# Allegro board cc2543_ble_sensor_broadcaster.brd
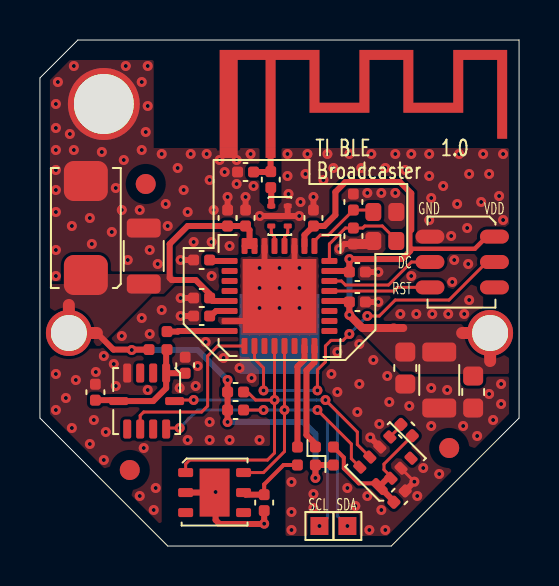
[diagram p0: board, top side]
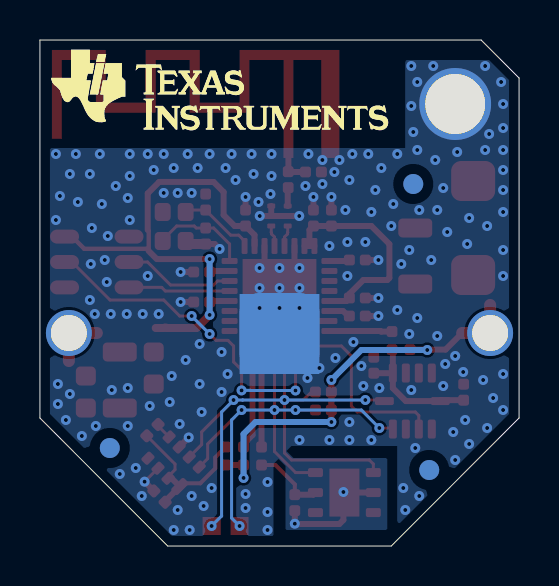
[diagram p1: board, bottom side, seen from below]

Outline 24 x 25.3 mm; copper layers: TOP, BOTTOM. Coordinates in mm from the lower left corner of the outline.
Outline path: 0,23.4 0,6.4 6.4,0 17.6,0 24,6.4 24,25.3 1.9,25.3 0,23.4

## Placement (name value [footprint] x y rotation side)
A1  2.4GHz  [ANTENNA_AN043CN]  11.55 19.65 0 top
BT1  3003  [BAT_3003C]  22.55 10.65 180 bottom
C2  22uF  [CAPC1608X90N]  18.3 9.7 270 top
C3  22uF  [CAPC1608X90N]  21.7 8.5 270 top
C4  100uF  [CAPC3216X180L]  5.2 13.1 90 top
C5  100uF  [CAPC3216X180L]  20 9.7 270 top
C6  470uF  [CAPMP6032X280L]  2.3 13.55 90 top
C21  100nF  [CAPC1005X60L]  11.23 2.57 270 top
C23  100nF  [CAPC1005X60L]  7.28 8.64 90 top
C24  1uF  [CAPC1005X60L]  2.78 7.29 90 top
C31  100nF  [CAPC1005X60L]  17.73 2.19 45 top
C41  DNM  [CAPC1005X60L]  10.7 18.7 180 top
C121  100nF  [CAPC1005X60L]  15.5 12.2 0 top
C151  100nF  [CAPC1005X60L]  15.5 13.7 0 top
C161  12pF  [CAPC1005X60L]  15.7 16.8 90 top
C171  12pF  [CAPC1005X60L]  15.7 15.9 270 top
C181  100nF  [CAPC1005X60L]  13.7 16 90 top
C231  220pF  [CAPC1005X60L]  9.4 16 90 top
C232  100nF  [CAPC1005X60L]  10.3 16 90 top
C291  100nF  [CAPC1005X60L]  8.5 12.4 180 top
C301  1uF  [CAPC1005X60L]  8.5 11.5 180 top
FIDU1  FIDU_1MM  [FID100X115]  5.3 18.1 0 top
FIDU2  FIDU_1MM  [FID100X115]  20.5 4.9 0 top
FIDU3  FIDU_1MM  [FID100X115]  4.5 3.8 0 top
FIDU4  FIDU_1MM  [FID100X115]  5.3 18.1 180 bottom
FIDU5  FIDU_1MM  [FID100X115]  20.5 4.9 180 bottom
FIDU6  FIDU_1MM  [FID100X115]  4.5 3.8 180 bottom
FL1  LFB182G45BG2D280  [FIL_LFB182G45BG2D280L]  11.59 17 270 top
J1  CLP-103-02-L-D  [SAMTEC_CLP10302LD-6L]  22.77 15.47 180 top
MH1  HOLE_3.0mm_PTH  [MTG300_360]  3.2 22.1 0 top
NOREF  -  []  0 17.03 0 top
NOREF#2  -  []  13.68 0 90 top
R1  4.7k  [RESC1005X40L]  10.2 7.7 180 top
R2  4.7k  [RESC1005X40L]  10.2 6.8 180 top
R11  0  [RESC1005X40BL]  6.36 9.82 180 top
R21  0  [RESC1005X40AL]  12.9 4.05 90 top
R31  0  [RESC1005X40BL]  14.7 4.95 270 top
R32  10k  [RESC1005X40L]  18.08 6.08 315 top
R41  0  [RESC1005X40L]  11.56 18.72 270 top
R251  56k  [RESC1005X40L]  7.7 14.3 0 top
TP1  TP_35SQU_SMD  [TP90SQWOPM_V2]  15.4 1 0 top
TP2  TP_35SQU_SMD  [TP90SQWOPM_V2]  14 1 0 top
U1  CC2543RHM  [QFNWB50P500X500X100-33CN]  10.25 10 0 top
U2  SHT21  [SON100P300X300X110-7L]  7.3 3.67 270 top
U3  T5400  [PSON71P223X278X75-8L]  16.99 2.97 45 top
U4  KXTF9  [QFNFC65P300X300X100-10N]  6.32 8.65 180 top
UNK#REFDES  -  []  22.44 24.82 180 bottom
X1  32MHz  [XTAL_FA128L]  16.7 16.7 270 top

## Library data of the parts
A1 = ANTENNA_AN043
BT1 = BATT_RETAINER: alternate symbols: (BAT_3003C,BAT_3003A)
C2 C3 = CAPACITOR: alternate symbols: (CAPC1608X90L,CAPC1608X90M)
C4 C5 = CAPACITOR: alternate symbols: (CAPC3216X180L,CAPC3216X180M)
C6 = CAPACITOR_POL: alternate symbols: (CAPMP6032X280L,CAPMP6032X280M)
C21 C23 C24 C31 C41 C121 C151 C161 C171 C181 C231 C232 C291 C301 = CAPACITOR: alternate symbols: (CAPC1005X60L,CAPC1005X60M)
FIDU1-FIDU6 = FIDMARK
FL1 = FILTER_LFB_6PIN: alternate symbols: (FIL_LFB182G45BG2D280L,FIL_LFB182G45BG2D280M)
J1 = CONN_HEADER_2X3: alternate symbols: (SAMTEC_CLP10302LD-6L,SAMTEC_CLP10302LD-6M)
MH1 = HOLE_PTH
R1 R2 R32 R41 R251 = RESISTOR: alternate symbols: (RESC1005X40L,RESC1005X40M)
R11 R21 R31 = RESISTOR_3PORTS: alternate symbols: (RESC1005X40AL,RESC1005X40AM,RESC1005X40BL,RESC1005X40BM)
TP1 TP2 = TEST_POINT
U1 = IC_RF_CC2543_QFN32_0: alternate symbols: (QFNWB50P500X500X100-33CL,QFNWB50P500X500X100-33CM)
U2 = IC_SENSOR_SHT21: alternate symbols: (SON100P300X300X110-7L,SON100P300X300X110-7M)
U3 = IC_PERIPH_T5400_PSON8: alternate symbols: (PSON71P223X278X75-8L,PSON71P223X278X75-8M)
U4 = IC_ACC_KXTF9_LGA10: alternate symbols: (QFNFC65P300X300X100-10,QFNFC65P300X300X100-10M)
X1 = XTAL_4: alternate symbols: (XTAL_FA128L,XTAL_FA128M)

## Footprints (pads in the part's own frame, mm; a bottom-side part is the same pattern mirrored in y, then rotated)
ANTENNA_AN043CN
  rect 0.5x0.5 smd: 1(0,0)
  rect 0.9x0.5 smd: 2(-2.1,0)
BAT_3003C
  round 2.3 hole 1.8: 1(0,0) 3(21.1,0)
  custom 1x1 smd: 2(10.55,0)
CAPC1005X60L
  custom 0.135x0.135 smd: 1(0,0) 2(0.8,0)
CAPC1608X90N
  custom 0.237x0.237 smd: 1(0,0) 2(1.6,0)
CAPC3216X180L
  custom 0.237x0.237 smd: 1(0,0) 2(2.8,0)
CAPMP6032X280L
  custom 0.5x0.5 smd: 1(0,0) 2(4.7,0)
FID100X115
  oval 1x1 smd: 1(0,0)
FIL_LFB182G45BG2D280L
  custom 0.062x0.062 smd: 1(0,0) 2(0.5,0) 3(1,0) 4(1,0.825) 5(0.5,0.825) 6(0,0.825)
MTG300_360
  round 3.6 hole 3: 1(0,0)
PSON71P223X278X75-8L
  custom 0.113x0.113 smd: 1(0,0) 2(0.71,-0.125) 3(1.42,-0.125) 4(2.13,-0.125) 5(2.13,1.375) 6(1.42,1.375) 7(0.71,1.375) 8(0,1.375)
QFNFC65P300X300X100-10N
  custom 0.1x0.1 smd: 1(0,0) 2(0.65,0) 3(1.3,0) 4(1.95,0) 5(2.375,1.4) 6(1.95,2.8) 7(1.3,2.8) 8(0.65,2.8) 9(0,2.8) 10(-0.425,1.4)
QFNWB50P500X500X100-33CN
  custom 0.075x0.075 smd: 1(0,0) 2(0.5,0) 3(1,0) 4(1.5,0) 5(2,0) 6(2.5,0) 7(3,0) 8(3.5,0) 9(4.25,0.75) 10(4.25,1.25) 11(4.25,1.75) 12(4.25,2.25) 13(4.25,2.75) 14(4.25,3.25) 15(4.25,3.75) 16(4.25,4.25) 17(3.5,5) 18(3,5) 19(2.5,5) 20(2,5) 21(1.5,5) 22(1,5) 23(0.5,5) 24(0,5) 25(-0.75,4.25) 26(-0.75,3.75) 27(-0.75,3.25) 28(-0.75,2.75) 29(-0.75,2.25) 30(-0.75,1.75) 31(-0.75,1.25) 32(-0.75,0.75)
  rect 3.7x3.7 smd: 33(1.75,2.5)
RESC1005X40AL
  custom 0.135x0.135 smd: 1(0,-0.9) 2(0,0) 3(0.9,0)
RESC1005X40BL
  custom 0.135x0.135 smd: 1(0,-0.9) 2(0,0) 3(0.9,0)
RESC1005X40L
  custom 0.135x0.135 smd: 1(0,0) 2(0.8,0)
SAMTEC_CLP10302LD-6L
  oval 1.45x0.7 smd: 1(0,0) 2(3.23,0) 3(0,1.27) 4(3.23,1.27) 5(0,2.54) 6(3.23,2.54)
SON100P300X300X110-7L
  custom 0.113x0.113 smd: 1(0,0) 2(1,0) 3(2,0) 4(2,2.9) 5(1,2.9) 6(0,2.9)
  rect 2.4x1.5 smd: 7(1,1.45)
TP90SQWOPM_V2
  rect 0.9x0.9 smd: 1(0,0)
XTAL_FA128L
  custom 0.2x0.2 smd: 1(0,0) 2(1.45,0) 3(1.45,1.15) 4(0,1.15)

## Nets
GND: A1.2(FEED) BT1.2(-) C2.2 C3.2 C4.2 C5.2 C6.2 C21.2 C23.2 C24.2 C31.2 C41.2 C121.2 C151.2 C161.2 C171.2 C181.2 C231.2 C232.2 C291.2 C301.2 FL1.2(GND#2) FL1.5(GND#5) FL1.6(GND#6) J1.2 MH1.1 R251.1 U1.19(VSS#19) U1.22(VSS#22) U1.31(VSS#31) U1.33(VSS/EGP) U2.2(VSS) U2.7(EGP) U3.3(GND) U3.6(MISO) U4.4(GND) X1.2 X1.4
VDD: BT1.1(+#1) BT1.3(+#3) C2.1 C3.1 C4.1 C5.1 C6.1 C121.1 C151.1 C181.1 C231.1 C232.1 C291.1 J1.1 R1.2 R2.2 R11.3 R21.1 R31.3 U1.12(VDD#12) U1.15(VDD#15) U1.18(VDD#18) U1.23(VDD#23) U1.24(VDD#24) U1.29(VDD#29)
ACC_INT: U1.1(P1_3) U4.7(INT)
ACC_POWER: R11.1 U1.32(P1_4)
DC: J1.4 U1.14(P2_2/DC)
DD: J1.3 U1.2(P2_1/DD)
HUM_POWER: R21.3 U1.7(P0_4)
PRS_POWER: R31.1 U1.8(P0_3)
RESET_N: J1.6 U1.13(NRESET)
SCL: R2.1 TP2.1 U1.5(P0_6) U2.6(SCL) U3.8(SCL/SCLK) U4.9(SCL)
SDA: R1.1 TP1.1 U1.4(P0_7) U2.1(SDA) U3.7(SDA/MOSI) U4.10(SDA)
N174685: FL1.4(BP2) U1.20(RF_P)
N174700: FL1.3(BP1) U1.21(RF_N)
N176560: R251.2 U1.25(RBIAS)
N176676: C301.1 U1.30(DCPL1)
N177477: C161.1 U1.17(XOSC_Q2) X1.1
N177564: C171.1 U1.16(XOSC_Q1) X1.3
N205771: C21.1 R21.2 U2.5(VDD)
N205894: C31.1 R31.2 R32.2 U3.1(VDD) U3.2(SEL)
N306707: FL1.1(UBP) R41.2
N306709: A1.1(GND) C41.1 R41.1
N309917: C23.1 C24.1 R11.2 U4.1(IOVDD) U4.5(VDD)
N318900: R32.1 U3.5(RST/SS)

Pads without a net: FIDU1 1; FIDU2 1; FIDU3 1; FIDU4 1; FIDU5 1; FIDU6 1; J1 5; U1 3 6 9 10 11 26 27 28; U2 3 4; U3 4; U4 2 3 6 8

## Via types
v1: diameter 0.5, hole 0.2, TOP to BOTTOM, 206 vias

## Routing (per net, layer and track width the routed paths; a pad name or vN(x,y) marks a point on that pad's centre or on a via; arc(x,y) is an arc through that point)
GND: length 26.5
  TOP w0.15: 18.09,3.88 v1(18.76,3.21)
  TOP w0.3: C291.2 v1(7.05,12.4) ; 18.29,2.75 v1(18.76,3.21) ; R251.1 v1(7.05,14.3) ; U1.19 12.75,13.25 U1.33 ; 11.23,1.77 v1(11.23,1.12) 11.22,1.1 9,1.1 8.8,1.3 8.8,2.62 U2.7 U2.2 ; C231.2 v1(9.4,17.45) ; FL1.5 FL1.6 ; FL1.5 FL1.2 v1(11.01,16.5) ; FL1.5 v1(12.99,16.5) ; U1.33 10.75,11.25 U1.31 ; U1.33 11.25,13.25 U1.22 ; U3.3 18.09,3.88 ; v1(15,14.85) 15.25,15.1 C171.2 ; C151.2 v1(16.95,13.7) ; C232.2 v1(10.3,17.45) ; C301.2 v1(7.05,11.5) ; 17.03,4.95 v1(16.55,5.43) ; C121.2 v1(16.95,12.2) ; C181.2 v1(13.7,17.45)
  TOP w0.5: C171.2 16.55,15.1 X1.2
  vias: v1(0.8,22.1) v1(0.8,20.9) v1(0.8,19.8) v1(0.8,18.8) v1(0.8,17.8) v1(0.8,16.7) v1(0.8,14.8) v1(0.8,13.5) v1(0.8,8.6) v1(0.8,6.8) v1(0.9,23.2) v1(1.3,7.4) v1(1.5,20.6) v1(1.6,16) v1(1.6,5.9) v1(1.7,24) v1(1.7,19.8) v1(1.8,8.3) v1(2.5,16.4) v1(2.5,5.1) v1(2.6,15.1) v1(2.7,6.3) v1(2.8,8.7) v1(3.1,19.7) v1(3.2,9.5) v1(3.2,4.3) v1(3.3,5.7) v1(3.6,15.7) v1(3.7,9.1) v1(3.8,17.9) v1(3.8,8) v1(4.1,16.8) v1(4.1,10.5) v1(4.2,19.3) v1(4.3,24) v1(4.4,14.3) v1(5,16.8) v1(5,2.5) v1(5.1,23.2) v1(5.1,19.8) v1(5.1,11.4) v1(5.2,4.9) v1(5.3,20.7) v1(5.4,24) v1(5.4,22) v1(5.4,7.8) v1(5.5,14.8) v1(5.5,10.6) v1(5.7,1.8) v1(5.8,2.9) v1(5.9,14.1) v1(6.1,19.6) v1(6.1,11.8) v1(6.3,17.1) v1(6.4,16) v1(6.9,18.9) v1(7,7.9) v1(7.2,17.8) v1(7.4,16.7) v1(7.4,5.3) v1(7.55,19.6) v1(7.7,15.2) v1(7.8,8) v1(7.9,9) v1(8.3,10.2) v1(8.35,19.6) v1(8.5,18.3) v1(8.5,6.2) v1(8.5,5.3) v1(8.6,15.2) v1(8.6,13.5) v1(8.7,16.8) v1(8.8,2.7) v1(9,19.3) v1(9.2,9.4) v1(9.25,18.7) v1(9.5,15) v1(9.5,5.3) v1(9.85,19.3) v1(9.85,18.1) v1(10,8.9) v1(10.55,19.6) v1(10.6,8.4) v1(10.7,18) v1(11,13.9) v1(11,12.9) v1(11,11.9) v1(11,5.3) v1(12,13.9) v1(12,12.9) v1(12,11.9) v1(12.4,19.6) v1(12.4,18.5) v1(12.45,17.6) v1(12.6,3.2) v1(12.6,1.7) v1(12.6,0.8) v1(13,13.9) v1(13,12.9) v1(13,11.9) v1(13.05,17.2) v1(13.3,18.6) v1(13.4,19.6) v1(13.7,2.6) v1(13.7,1.9) v1(14.2,18.3) v1(14.4,19.6) v1(14.6,8.6) v1(14.7,18.9) v1(14.9,9.7) v1(14.9,7.7) v1(15.4,2.9) v1(15.5,19.6) v1(15.8,2) v1(15.9,6.7) v1(16,10.1) v1(16,8.1) v1(16.1,18.9) v1(16.4,17.65) v1(16.4,2.5) v1(16.5,0.8) v1(16.6,19.6) v1(16.7,9.3) v1(17,6.1) v1(17.1,17.65) v1(17.1,1.8) v1(17.3,18.9) v1(17.3,0.8) v1(17.4,8.5) v1(17.5,7.2) v1(17.8,19.6) v1(17.8,17.65) v1(18.05,11.6) v1(18.3,18.8) v1(18.5,7) v1(18.6,19.6) v1(18.6,13.5) v1(18.85,11.6) v1(18.9,2.5) v1(19.2,3.9) v1(19.5,19.6) v1(19.5,18.5) v1(19.5,16.3) v1(19.6,17.4) v1(19.6,7.9) v1(19.6,6) v1(19.65,11.6) v1(20,3.6) v1(20.2,18) v1(20.4,7.8) v1(20.45,11.6) v1(20.6,15.5) v1(20.65,13.2) v1(20.75,14.3) v1(20.9,17.1) v1(21,19.6) v1(21.2,6) v1(21.25,11.6) v1(21.4,15.9) v1(21.5,18.6) v1(21.45,14.1) v1(21.5,12.3) v1(21.9,5.5) v1(22.1,17.2) v1(22.2,19.6) v1(22.5,18.6) v1(22.5,7.6) v1(22.7,6.3) v1(23,17.5) v1(23.1,8.1) v1(23.1,7.1) v1(23.2,19.6) v1(23.2,16.3)
VDD: length 64.4
  TOP w0.15: 3.68,9.82 3.7,9.8 v1(4.6,9.8) ; C3.1 21.7,8.7
  TOP w0.22: J1.1 22.39,15.47 21.78,14.86 18.66,14.86 18.55,14.75 18.55,15.75 18.6,15.8 ; 18.15,14.35 18.1,14.35
  TOP w0.3: 18.1,14.35 v1(15.5,14.35) C151.1 ; R11.3 3.68,9.82 2.85,10.65 ; 10.5,15 10.5,15.8 C232.1 C231.1 7.4,16 6.5,15.1 6.5,13.4 6.6,13.3 7.8,13.3 8.5,12.6 C291.1 8.65,12.25 U1.29 ; 10.5,15 U1.24 ; 10.5,15 U1.23 ; C151.1 15.45,13.65 ; C151.1 15.45,13.75 U1.15 ; U1.18 13.25,15.55 C181.1 14.25,16 14.8,16.55 14.8,17.7 15.3,18.2 16.17,18.2 16.17,18.2 18.03,18.2 18.6,17.63 18.6,15.8 ; U1.12 15.45,12.25 C121.1 ; v1(9.4,6.2) R2.2 R1.2 v1(9.4,8.3) ; C121.1 v1(15.5,11.55) ; C121.1 15.45,12.15 ; 18.55,14.75 18.15,14.35 ; R31.3 R21.1 v1(13.8,3.4)
  TOP w0.4: 18.2,10.9 17.83,10.9 17.76,10.91 17.67,10.91 17.61,10.9 17.6,10.9 16.2,10.9 ; 16.15,10.9 15.55,11.5 15.55,11.51 v1(15.5,11.55)
  TOP w0.6: 22.55,9.25 BT1.1 21.15,10.65 ; 2.85,10.65 BT1.3 1.45,12.05
  BOTTOM w0.3: v1(9.4,8.3) 7.9,9.8 v1(4.6,9.8) ; v1(9.4,6.2) 13.2,6.2 13.8,5.6 v1(13.8,3.4) ; v1(15.5,11.55) v1(15.5,14.35)
ACC_INT: length 8.8
  TOP w0.15: U1.1 8.9,10 8.4,9.5 8.4,7 8.1,6.7 5.2,6.7 5.02,6.52 U4.7
ACC_POWER: length 3.1
  TOP w0.3: U1.32 6.94,10.75 6.91,10.72 R11.1
DC: length 5.6
  TOP w0.15: U1.14 15.1,13.25 15.3,13.05 17.46,13.05 18.61,14.2 J1.4
DD: length 17.7
  TOP w0.15: v1(15.5,10.6) 15.18,10.28 14.58,10.28 14.3,10 14.3,9.2 13.9,8.8 v1(13.9,7.78) ; v1(11.2,7.77) 11.2,8.9 10.75,9.35 U1.2 ; v1(16.4,11.5) 17,11.5 17.8,12.3 20.49,12.3 22.39,14.2 J1.3
  BOTTOM w0.15: v1(15.5,10.6) v1(16.4,11.5) ; v1(11.2,7.77) 13.44,7.77 13.45,7.78 v1(13.9,7.78)
HUM_POWER: length 5.2
  TOP w0.3: U1.7 13.25,9.32 12.9,8.97 R21.3
PRS_POWER: length 5.4
  TOP w0.3: R31.1 13.8,5.1 13.35,5.55 13.35,8.79 13.75,9.18 U1.8
RESET_N: length 5.1
  TOP w0.15: U1.13 17.72,12.75 17.9,12.93 J1.6
SCL: length 26.6
  TOP w0.15: v1(11.2,6.8) R2.1 ; U4.9 6.38,5.9 v1(7,5.9) ; U2.6 11.2,3.67 12.25,4.73 v1(12.25,6.8) U1.5 ; 16.02,3.94 15.6,4.37 15.6,5.1 v1(13.9,6.8)
  BOTTOM w0.15: v1(14,1) 14.4,1.4 14.4,6.3 v1(13.9,6.8) v1(12.25,6.8) v1(11.2,6.8) 7.9,6.8 v1(7,5.9)
SDA: length 30.3
  TOP w0.15: v1(11.75,7.3) 10.8,7.3 10.4,7.7 R1.1 ; v1(11.75,7.3) U1.4 ; v1(11.75,7.3) 11.75,4.65 11.4,4.3 7.5,4.3 7.3,4.1 U2.1 ; v1(7.7,7.3) 6.8,7.3 U4.10 ; v1(14.3,7.3) 15.9,5.7 15.9,5.07 U3.7
  BOTTOM w0.15: v1(15.4,1) 14.9,1.5 14.9,6.7 v1(14.3,7.3) 13.85,7.3 13.85,7.3 v1(11.75,7.3) v1(7.7,7.3)
N174685: length 1.1
  TOP w0.15: FL1.4 12.41,15.67 12.4,15.66 12.4,15.6 12.25,15.45 U1.20
N174700: length 1.1
  TOP w0.15: FL1.3 11.59,15.67 11.6,15.66 11.6,15.6 11.75,15.45 U1.21
N176560: length 1
  TOP w0.3: R251.2 8.55,14.25 U1.25
N176676: length 1.1
  TOP w0.15: C301.1 8.55,11.5 8.62,11.57
  TOP w0.3: U1.30 8.82,11.75 8.62,11.57
N177477: length 3.9
  TOP w0.15: U1.17 13.75,15.25 14.04,15.54 14.45,15.54 15.7,16.8 C161.1 16.6,16.8 X1.1 16.7,16.75
N177564: length 5.1
  TOP w0.15: C171.1 15.3,15.9 14.5,15.1 U1.16 ; C171.1 15.7,15.89 ; C171.1 16.17,15.9 16.27,16 17.15,16 17.85,15.3 X1.3 ; C171.1 15.7,15.9 15.5,15.9 15.5,15.9
N205771: length 3.7
  TOP w0.2: R21.2 12.2,4.05 11.23,3.08 C21.1
  TOP w0.3: 10.2,2.67 U2.5 10.3,2.57 C21.1
N205894: length 8.2
  TOP w0.15: U3.2 17.58,3.46 17.23,3.81 17.23,4.1 R32.2
  TOP w0.2: R31.2 14.7,4.94 15.22,4.42 15.22,3.88 15.97,3.13 16.83,3.13 U3.1 16.93,2.97
  TOP w0.3: U3.2 17.41,3.39 U3.1 17.73,2.24 C31.1
N306707: length 0.9
  TOP w0.3: R41.2 11.59,17.89 FL1.1
N306709: length 1.8
  TOP w0.3: A1.1 11.55,18.73 R41.1 11.54,18.7 C41.1
N309917: length 6.7
  TOP w0.3: C23.1 6.33,8.64 U4.1 ; U4.1 6.32,7.89 5.68,7.25 U4.5 3.9,7.29 C24.1 ; U4.1 6.32,9.78 R11.2
N318900: length 0.9
  TOP w0.15: U3.5 18.08,6.01 R32.1

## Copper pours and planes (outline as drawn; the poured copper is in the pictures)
GND on BOTTOM (solid shape): 14,8.6 10,8.6 10,12.6 14,12.6
GND on TOP: 12.3,0.5 12.3,3.7 11.9,3.7 11.9,5 6.1,5 6.1,1.01 0.5,6.61 0.5,23.3 1.5,24.3 5.7,24.3 5.7,19.9 11,19.9 11,17.2 11.3,16.9 11.8,16.9 12.1,17.2 12.1,19.9 23.5,19.9 23.5,14.1 22.2,14.1 22.2,11.7 23.5,11.7 23.5,6.61 20.7,3.81 20.7,4 20.6,4 20.6,3.71 17.39,0.5 ; 3 cut-outs
GND on BOTTOM: 12.3,0.5 12.3,4.1 12.05,4.35 11.7,4 11.7,0.8 6.6,0.8 6.6,4.4 11.3,4.4 11.65,4.75 11.4,5 6.1,5 6.1,1.01 0.5,6.61 0.5,23.3 1.5,24.3 5.7,24.3 5.7,19.9 23.5,19.9 23.5,6.61 17.39,0.5 ; 4 cut-outs
VDD on TOP: 0.5,10 0.5,13.1 1.3,13.1 1.8,13.6 6.6,13.6 6.8,13.4 6.8,13.2 6.2,12.6 5.6,12.6 3,10
VDD on TOP: 18.2,8.6 15.7,11.1 23.5,11.1 23.5,8.6
Net_7 on TOP (solid shape): 14,22.16 16,22.16 16,24.8 18.7,24.8 18.7,22.16 20.7,22.16 20.7,24.8 23.4,24.8 23.4,20.36 22.9,20.36 22.9,24.3 21.2,24.3 21.2,21.66 18.2,21.66 18.2,24.3 16.5,24.3 16.5,21.66 13.5,21.66 13.5,24.3 11.8,24.3 11.8,19.9 11.3,19.9 11.3,24.3 9.9,24.3 9.9,19.9 9,19.9 9,24.8 14,24.8

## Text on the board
Ref Des/Silkscreen Top: SCL | SDA | DC | RST | GND | VDD | TI BLE | Broadcaster | 1.0
XSECTION_CHART: L1: TOP CONDUCTOR - COPPER 0.035 MM | *  DIELECTRIC - FR-4 1.14 MM | L2: BOTTOM CONDUCTOR - COPPER 0.035 MM | DESIGN CROSS SECTION CHART | ___________________________ | TOTAL THICKNESS 1.21 MM
NCLEGEND-1-2: FIGURE | SIZE | 0.2 | 1.8 | 3.0 | DRILL CHART: TOP to BOTTOM | ALL UNITS ARE IN MILLIMETERS | PLATED | QTY | 206 | 2 | 1
